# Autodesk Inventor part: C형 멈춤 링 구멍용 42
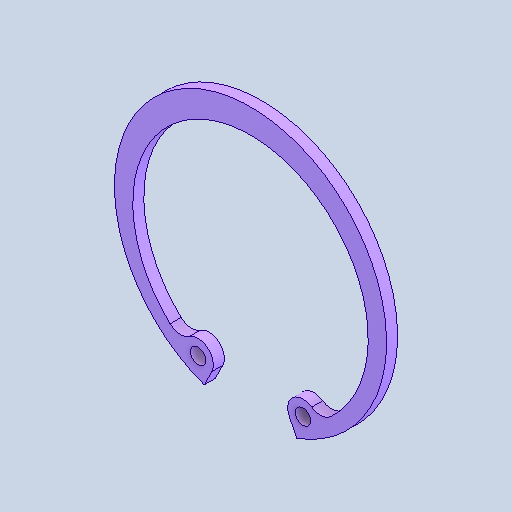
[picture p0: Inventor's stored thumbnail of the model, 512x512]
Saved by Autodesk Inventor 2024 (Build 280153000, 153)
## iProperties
Created: 2025-11
Part Number: C형 멈춤 링 구멍용 42
Material: 강철, 연강
Description: 리테이닝 링(C형)
Document SubType Name: Modeling
Designer: Eud07
Density: 7.85 g/cm^3
Appearance: 기본값
Author: jhkim
Sending System: Autodesk Inventor 2026
Preprocessor: ST-DEVELOPER v20.1
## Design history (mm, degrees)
node "C형 멈춤링 구멍용 421"
node "솔리드1"
body "Solid1"
